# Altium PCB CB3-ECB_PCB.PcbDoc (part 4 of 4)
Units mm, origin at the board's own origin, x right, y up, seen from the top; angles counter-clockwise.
Board outline 195 x 139 mm, 4 copper layers (Top Layer, Layer 1, Layer 2, Bottom Layer), stack 1.56 mm thick; 363 components, 264 nets, 1430 pads, 630 vias.
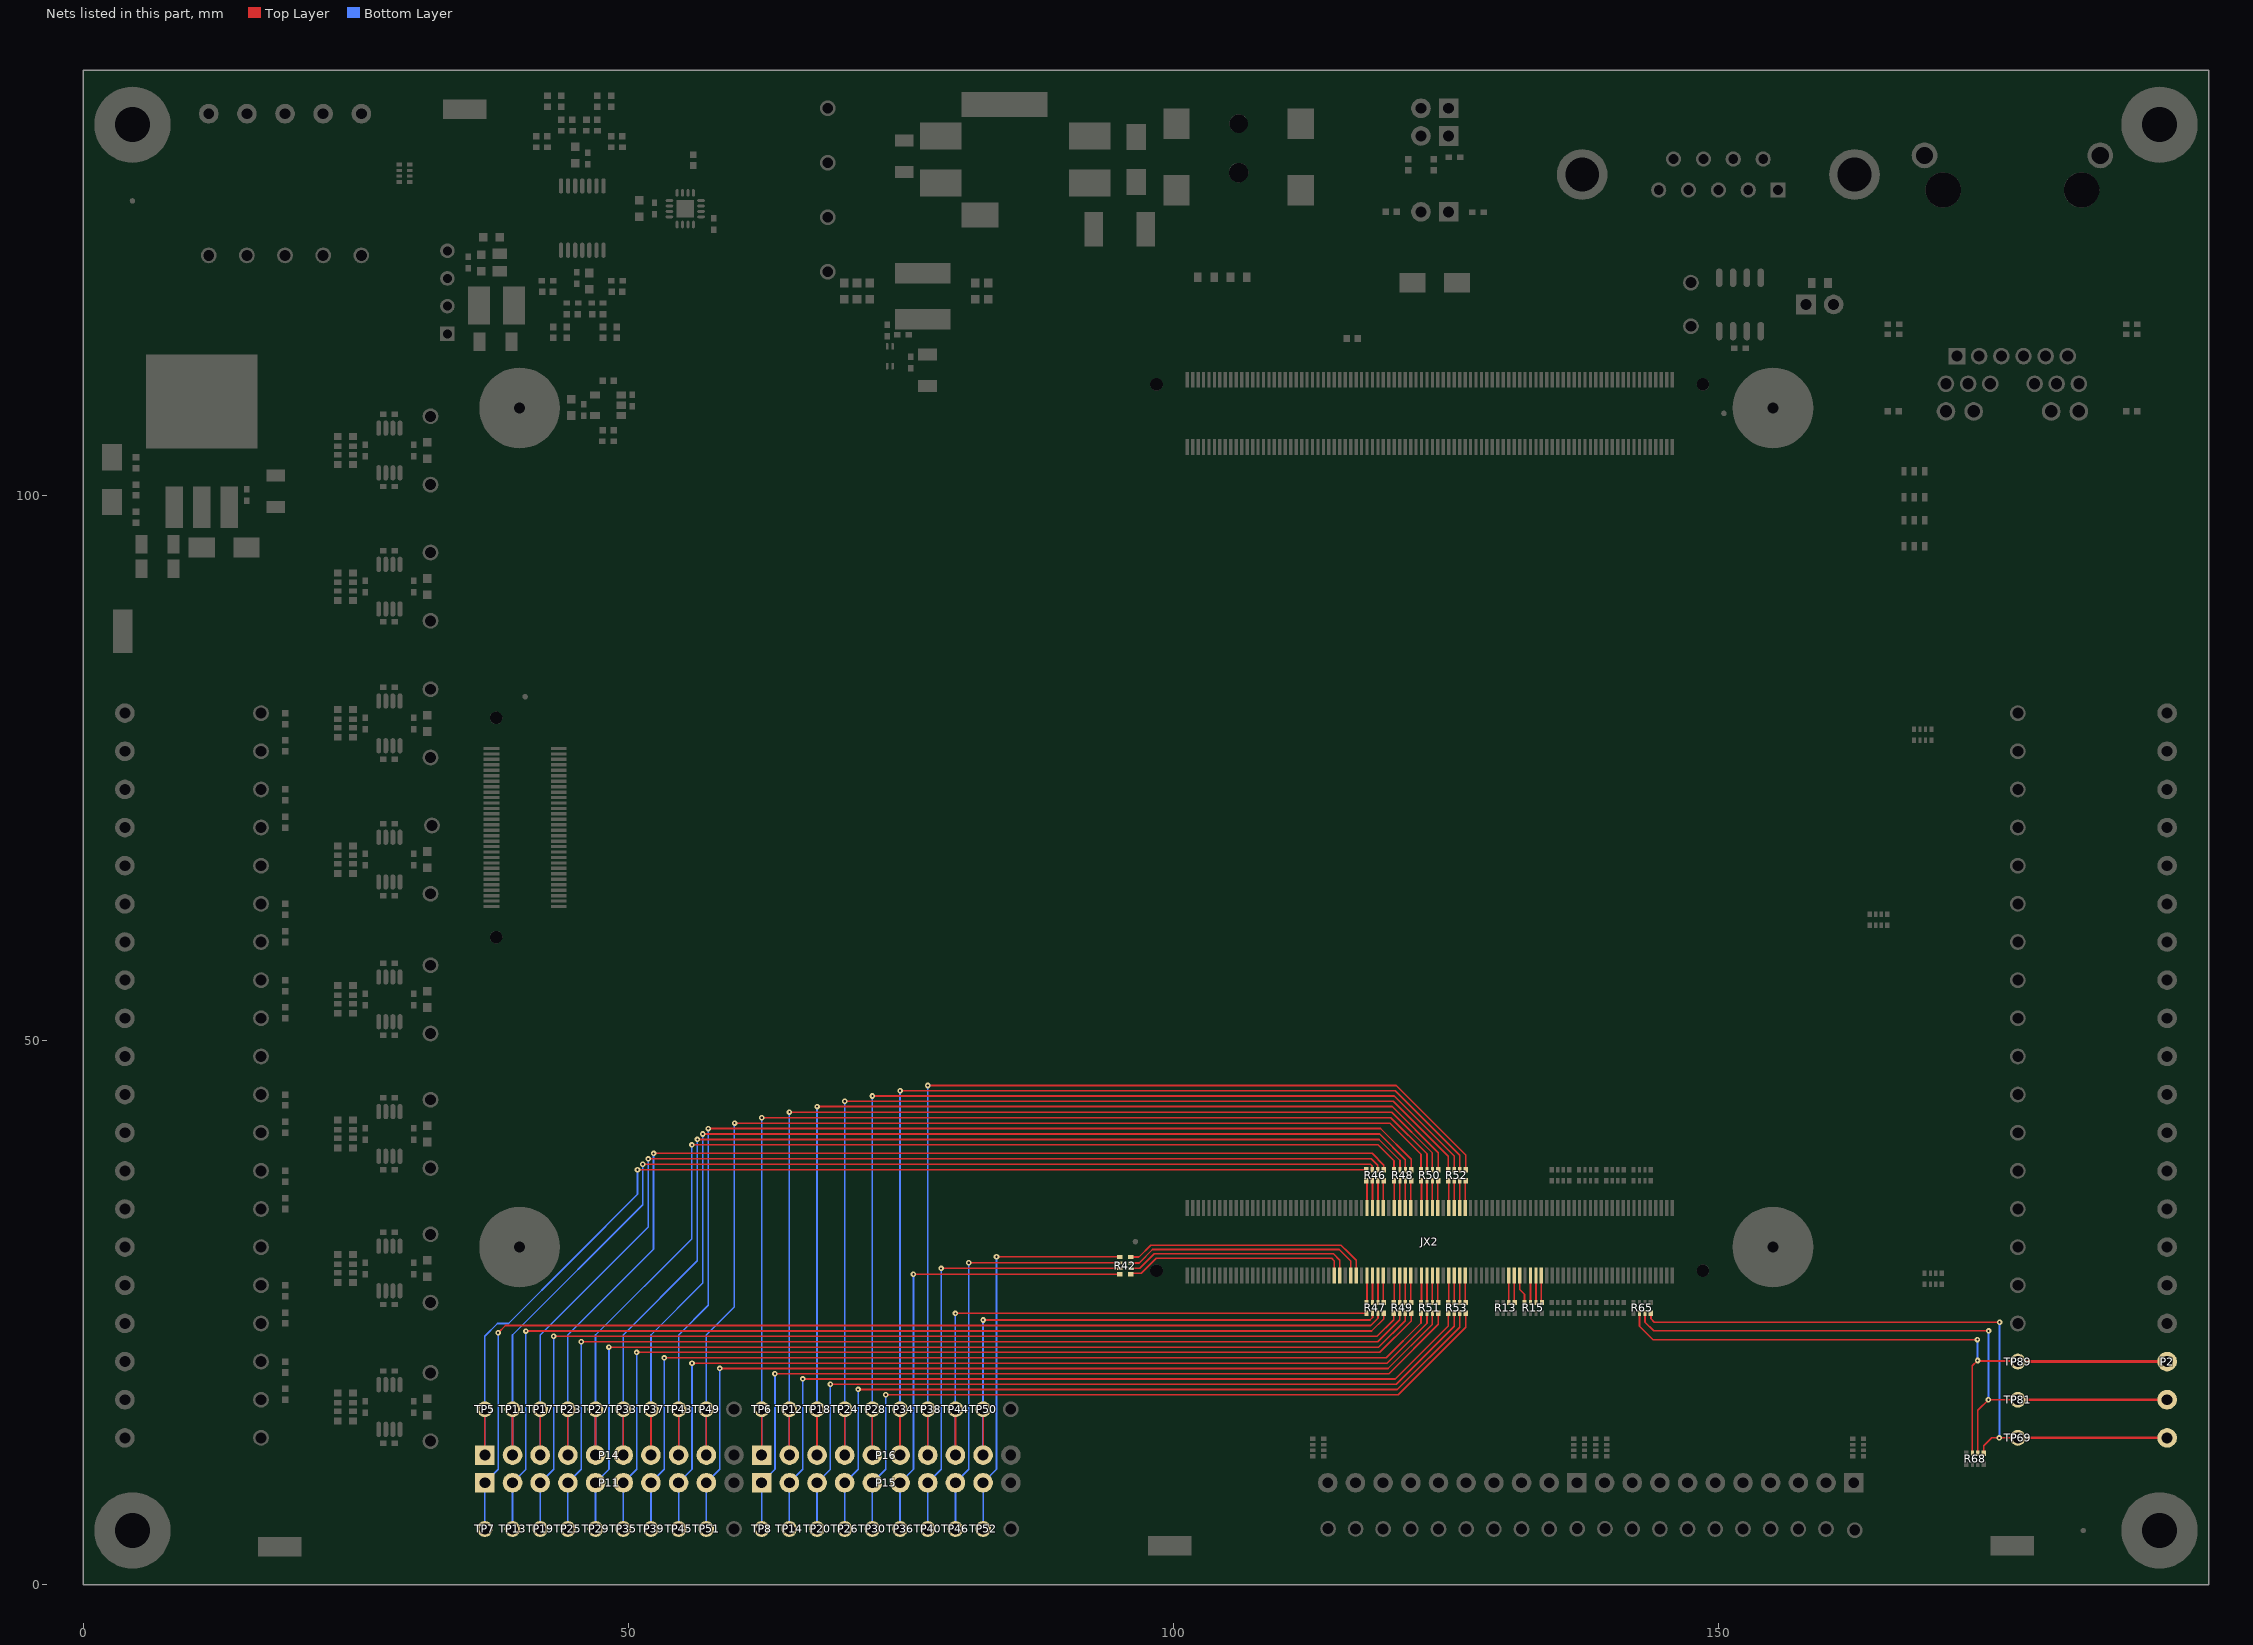
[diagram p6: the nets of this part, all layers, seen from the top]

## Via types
v1: diameter 0.508, hole 0.2, Top Layer to Bottom Layer, tented both sides, 435 vias
v2: diameter 0.508, hole 0.2, Top Layer to Bottom Layer, 194 vias
v3: diameter 0.66, hole 0.33, Top Layer to Bottom Layer, tented both sides, 1 vias

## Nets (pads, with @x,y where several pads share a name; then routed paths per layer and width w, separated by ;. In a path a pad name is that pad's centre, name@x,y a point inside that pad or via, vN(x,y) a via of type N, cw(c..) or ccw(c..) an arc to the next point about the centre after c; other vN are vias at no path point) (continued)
PWM-13: P2.3 R65.2 R68.3 TP89.1 | length 60.8
  Top Layer w0.152: R65.2@142.78,24.92 142.78,23.752 144.016,22.516 v1(173.794,22.516) ; R68.3@173.328,12.073 173.328,20.128 v1(173.8,20.6) 173.85,20.55 177.45,20.55 TP89.1@177.5,20.5
  Top Layer w0.25: TP89.1@177.5,20.5 P2.3@191.2,20.5
  Bottom Layer w0.152: v1(173.794,22.516) 173.797,22.514 173.797,20.603 v1(173.8,20.6)
PWM-14: P2.4 R65.3 R68.2 TP81.1 | length 60.7
  Top Layer w0.152: R65.3@143.28,24.92 143.28,24.117 144.083,23.315 v1(174.81,23.315) ; R68.2@173.828,12.073 173.828,16.028 v1(174.8,17) TP81.1@177.5,17
  Top Layer w0.25: TP81.1@177.5,17 P2.4@191.2,17
  Bottom Layer w0.152: v1(174.8,17) 174.805,17.005 174.805,23.31 v1(174.81,23.315)
PWM-15: P2.5 R65.4 R68.1 TP69.1 | length 61.1
  Top Layer w0.152: R65.4@143.83,24.92 143.83,24.432 144.149,24.113 v1(175.826,24.113) ; R68.1@174.378,12.073 174.378,12.784 175.094,13.5 TP69.1@177.5,13.5
  Top Layer w0.25: TP69.1@177.5,13.5 P2.5@191.2,13.5
  Bottom Layer w0.152: v1(175.8,13.5) 175.813,13.513 175.813,24.1 v1(175.826,24.113)
SPI1_LATCH: JX2.121 R13.2 | length 2.5
  Top Layer w0.152: R13.2@130.78,25.92 JX2.121@130.78,28.41
SPI1_MISO: JX2.120 R13.1 | length 2.5
  Top Layer w0.152: JX2.120@131.28,28.41 131.28,25.97 R13.1@131.33,25.92
SPI1_MOSI: JX2.116 R15.2 | length 2.5
  Top Layer w0.152: R15.2@133.28,25.92 JX2.116@133.28,28.41
SPI1_nCS: JX2.117 R15.3 | length 2.5
  Top Layer w0.152: R15.3@132.78,25.92 JX2.117@132.78,28.41
SPI1_nRST: JX2.115 R15.1 | length 2.5
  Top Layer w0.152: JX2.115@133.78,28.41 133.78,25.97 R15.1@133.83,25.92
SPI1_SCLK: JX2.119 R15.4 | length 2.7
  Top Layer w0.152: JX2.119@131.78,28.41 131.78,27.12 132.23,26.67 R15.4@132.23,25.92
USER0: P14.1 R46.4 TP5.1 | length 104.3
  Top Layer w0.152: P14.1@36.834,11.921 TP5.1@36.834,16.76 ; v1(50.843,38.096) R46.4@117.72,38.096
  Bottom Layer w0.152: P14.1@36.834,11.921 36.834,16.76 36.834,17.954 36.834,22.834 38,24 39,24 45.041,30.041 50.843,35.843 v1(50.843,38.096)
USER1: P14.2 R46.3 TP11.1 | length 103.1
  Top Layer w0.152: P14.2@39.374,11.921 TP11.1@39.374,16.76 ; v1(51.327,38.603) 117.671,38.603 118.096,38.603 118.27,38.429 R46.3@118.27,38.096
  Bottom Layer w0.152: P14.2@39.374,11.921 TP11.1@39.374,16.024 ; TP11.1@39.374,16.786 39.374,20.24 39.374,22.945 51.327,34.897 v1(51.327,38.603)
USER2: P14.3 R46.2 TP17.1 | length 103.7
  Top Layer w0.152: P14.3@41.914,11.921 TP17.1@41.914,16.76 ; v1(51.82,39.103) 117.837,39.103 118.171,39.103 118.77,38.503 R46.2@118.77,38.096
  Bottom Layer w0.152: P14.3@41.914,11.921 41.914,16.938 41.914,22.945 51.82,32.851 v1(51.82,39.103)
USER3: P14.4 R46.1 TP23.1 | length 103.7
  Top Layer w0.152: P14.4@44.454,11.921 TP23.1@44.454,16.76 ; v1(52.314,39.603) 118.246,39.603 119.32,38.528 R46.1@119.32,38.096
  Bottom Layer w0.152: P14.4@44.454,11.921 44.454,22.945 52.314,30.804 v1(52.314,39.603)
USER4: P14.5 R48.4 TP27.1 | length 102.8
  Top Layer w0.152: P14.5@46.994,11.921 TP27.1@46.994,16.76 ; v1(55.834,40.381) 118.8,40.381 120.252,38.929 R48.4@120.252,38.096
  Bottom Layer w0.152: P14.5@46.994,11.921 46.994,22.945 55.834,31.785 v1(55.834,40.381)
USER5: P14.6 R48.3 TP33.1 | length 102.7
  Top Layer w0.152: P14.6@49.534,11.921 TP33.1@49.534,16.76 ; v1(56.334,40.881) 118.875,40.881 120.802,38.954 R48.3@120.802,38.096
  Bottom Layer w0.152: P14.6@49.534,11.921 49.534,22.945 56.334,29.745 v1(56.334,40.881)
USER6: P14.7 R48.2 TP37.1 | length 102.6
  Top Layer w0.152: P14.7@52.074,11.921 TP37.1@52.074,16.76 ; v1(56.834,41.381) 118.95,41.381 121.302,39.028 R48.2@121.302,38.096
  Bottom Layer w0.152: P14.7@52.074,11.921 52.074,22.945 56.834,27.705 v1(56.834,41.381)
USER7: P14.8 R48.1 TP43.1 | length 102.6
  Top Layer w0.152: P14.8@54.614,11.921 TP43.1@54.614,16.76 ; v1(57.334,41.881) 119.025,41.881 121.852,39.053 R48.1@121.852,38.096
  Bottom Layer w0.152: P14.8@54.614,11.921 54.614,22.945 57.334,25.665 v1(57.334,41.881)
USER8: P14.9 R50.4 TP49.1 | length 102
  Top Layer w0.152: P14.9@57.154,11.921 TP49.1@57.154,16.76 ; v1(59.745,42.381) 119.887,42.381 122.73,39.538 R50.4@122.73,38.096
  Bottom Layer w0.152: P14.9@57.154,11.921 57.154,22.945 59.734,25.525 v1@59.734,42.381
USER9: P16.1 R50.3 TP6.1 | length 99.7
  Top Layer w0.152: P16.1@62.234,11.921 TP6.1@62.234,16.76 ; v1(62.234,42.881) 119.656,42.881 119.962,42.881 123.28,39.562 R50.3@123.28,38.096
  Bottom Layer w0.152: P16.1@62.23,11.921 62.23,16.166 62.23,18.195 v1@62.23,42.881
USER10: P16.2 R50.2 TP12.1 | length 98.4
  Top Layer w0.152: P16.2@64.774,11.921 TP12.1@64.774,16.76 ; v1@64.774,43.381 120.036,43.381 123.78,39.637 R50.2@123.78,38.096
  Bottom Layer w0.152: P16.2@64.77,11.925 64.77,16.166 64.77,18.28 64.77,42.881 64.77,43.388 v1(64.774,43.392)
USER11: P16.3 R50.1 TP18.1 | length 97.2
  Top Layer w0.152: P16.3@67.314,11.921 TP18.1@67.314,16.76 ; v1@67.314,43.903 119.783,43.903 120.089,43.903 124.33,39.662 R50.1@124.33,38.096
  Bottom Layer w0.152: P16.3@67.31,11.925 67.31,16.166 67.31,18.195 67.31,42.381 67.31,43.896 v1(67.314,43.9)
USER12: P16.4 R52.4 TP24.1 | length 96
  Top Layer w0.152: P16.4@69.854,11.921 TP24.1@69.854,16.76 ; v1(69.854,44.386) 119.952,44.386 120.181,44.386 125.23,39.337 R52.4@125.23,38.096
  Bottom Layer w0.152: P16.4@69.85,11.925 69.85,16.166 69.85,18.195 v1@69.85,44.386
USER13: P16.5 R52.3 TP28.1 | length 94.7
  Top Layer w0.152: P16.5@72.394,11.921 TP28.1@72.394,16.76 ; v1(72.394,44.868) 120.12,44.868 120.273,44.868 125.78,39.361 R52.3@125.78,38.096
  Bottom Layer w0.152: P16.5@72.39,11.925 72.39,16.166 72.39,18.195 v1@72.39,44.868
USER14: P16.6 R52.2 TP34.1 | length 93.4
  Top Layer w0.152: P16.6@74.934,11.921 TP34.1@74.934,16.76 ; v1(74.934,45.351) 120.288,45.351 120.365,45.351 126.28,39.436 R52.2@126.28,38.096
  Bottom Layer w0.152: P16.6@74.93,11.925 74.93,16.166 v1@74.93,45.351
USER15: P16.7 R52.1 TP38.1 | length 92.1
  Top Layer w0.152: v1(77.47,45.834) 120.016,45.834 120.458,45.834 126.83,39.461 R52.1@126.83,38.096 ; P16.7@77.474,11.921 TP38.1@77.474,16.76
  Bottom Layer w0.152: P16.7@77.47,11.925 77.47,16.166 77.47,18.195 v1(77.47,45.834)
USER16: P16.8 R47.1 TP44.1 | length 55.6
  Top Layer w0.152: P16.8@80.014,11.921 TP44.1@80.014,16.76 ; v1@80.014,24.924 R47.1@117.73,24.92
  Bottom Layer w0.152: P16.8@80.01,11.925 v1(80.01,24.924)
USER17: P16.9 R47.2 TP50.1 | length 53.4
  Top Layer w0.152: v1(82.55,24.316) 117.987,24.316 118.057,24.316 118.28,24.539 R47.2@118.28,24.92 ; P16.9@82.554,11.921 TP50.1@82.554,16.76
  Bottom Layer w0.152: P16.9@82.55,11.925 v1(82.55,24.316)
USER18: P11.1 R47.3 TP7.1 | length 100.2
  Top Layer w0.152: v1@38.058,23.143 38.727,23.812 117.788,23.812 118.127,23.812 118.78,24.465 R47.3@118.78,24.92
  Bottom Layer w0.152: TP7.1@36.834,5.143 P11.1@36.834,9.381 38.063,10.61 38.063,23.138 v1(38.054,23.148)
USER19: P11.2 R47.4 TP13.1 | length 98.3
  Top Layer w0.152: v1(40.603,23.304) 117.981,23.304 118.194,23.304 119.33,24.44 R47.4@119.33,24.92
  Bottom Layer w0.152: TP13.1@39.374,5.143 P11.2@39.374,9.381 40.603,10.61 v1(40.603,23.304)
USER20: P11.3 R49.1 TP19.1 | length 96.5
  Top Layer w0.152: v1@43.143,22.821 118.351,22.821 118.702,22.821 120.23,24.349 R49.1@120.23,24.92
  Bottom Layer w0.152: TP19.1@41.914,5.143 P11.3@41.914,9.381 43.143,10.61 v1(43.143,22.818)
USER21: P11.4 R49.2 TP25.1 | length 94.2
  Top Layer w0.152: v1(45.683,22.313) 118.519,22.313 118.769,22.313 120.78,24.325 R49.2@120.78,24.92
  Bottom Layer w0.152: TP25.1@44.454,5.143 P11.4@44.454,9.381 45.683,10.61 v1(45.683,22.313)
USER22: P11.5 R49.3 TP29.1 | length 91.9
  Top Layer w0.152: v1(48.223,21.831) 118.687,21.831 118.861,21.831 121.28,24.25 R49.3@121.28,24.92
  Bottom Layer w0.152: TP29.1@46.994,5.143 P11.5@46.994,9.381 48.223,10.61 v1(48.223,21.831)
USER23: P11.6 R49.4 TP35.1 | length 89.7
  Top Layer w0.152: v1@50.763,21.348 118.953,21.348 121.83,24.225 R49.4@121.83,24.92
  Bottom Layer w0.152: TP35.1@49.534,5.143 P11.6@49.534,9.381 50.763,10.61 v1(50.763,21.344)
USER24: P11.7 R51.1 TP39.1 | length 87.8
  Top Layer w0.152: v1(53.303,20.84) 119.532,20.84 122.73,24.038 R51.1@122.73,24.92
  Bottom Layer w0.152: TP39.1@52.074,5.143 P11.7@52.074,9.381 53.303,10.61 v1(53.303,20.84)
USER25: P11.8 R51.2 TP45.1 | length 85.6
  Top Layer w0.152: v1(55.843,20.354) 119.164,20.354 119.621,20.354 123.28,24.013 R51.2@123.28,24.92
  Bottom Layer w0.152: TP45.1@54.614,5.143 P11.8@54.614,9.381 55.843,10.61 v1(55.843,20.354)
USER26: P11.9 R51.3 TP51.1 | length 83.3
  Top Layer w0.152: v1(58.383,19.871) 61.041,19.871 119.713,19.871 123.78,23.939 R51.3@123.78,24.92
  Bottom Layer w0.152: TP51.1@57.154,5.143 P11.9@57.154,9.381 58.383,10.61 v1(58.383,19.871)
USER27: P15.1 R51.4 TP8.1 | length 78.5
  Top Layer w0.152: v1(63.454,19.389) 119.805,19.389 124.33,23.914 R51.4@124.33,24.92
  Bottom Layer w0.152: TP8.1@62.234,5.143 P15.1@62.234,9.381 63.463,10.61 v1@63.463,19.389
USER28: P15.2 R53.1 TP14.1 | length 76.7
  Top Layer w0.152: v1(66.003,18.906) 120.375,18.906 125.23,23.761 R53.1@125.23,24.92
  Bottom Layer w0.152: TP14.1@64.774,5.143 P15.2@64.774,9.381 66.003,10.61 v1(66.003,18.906)
USER29: P15.3 R53.2 TP20.1 | length 74.5
  Top Layer w0.152: v1@68.543,18.246 68.721,18.423 119.989,18.423 120.467,18.423 125.78,23.737 R53.2@125.78,24.92
  Bottom Layer w0.152: TP20.1@67.314,5.143 P15.3@67.314,9.381 68.543,10.61 v1(68.543,18.423)
USER30: P15.4 R53.3 TP26.1 | length 72.1
  Top Layer w0.152: v1(71.083,17.941) 120.082,17.941 120.559,17.941 126.28,23.662 R53.3@126.28,24.92
  Bottom Layer w0.152: TP26.1@69.854,5.143 P15.4@69.854,9.381 71.083,10.61 v1(71.083,17.941)
USER31: P15.5 R53.4 TP30.1 | length 69.9
  Top Layer w0.152: v1(73.623,17.458) 120.174,17.458 120.651,17.458 126.83,23.637 R53.4@126.83,24.92
  Bottom Layer w0.152: TP30.1@72.394,5.143 P15.5@72.394,9.381 73.623,10.61 v1(73.623,17.458)
USER32: P15.6 R42.4 TP36.1 | length 42.8
  Top Layer w0.152: v1(76.163,28.512) 95.088,28.512 R42.4@95.1,28.5
  Bottom Layer w0.152: TP36.1@74.934,5.143 P15.6@74.934,9.381 76.163,10.61 v1(76.163,28.512)
USER33: P15.7 R42.3 TP40.1 | length 40.8
  Top Layer w0.152: v1@78.703,29.062 95.088,29.062 R42.3@95.1,29.05
  Bottom Layer w0.152: TP40.1@77.474,5.143 P15.7@77.474,9.381 78.703,10.61 v1(78.703,29.054) v1@78.703,29.062
USER34: P15.8 R42.2 TP46.1 | length 38.8
  Top Layer w0.152: v1(81.243,29.562) 95.088,29.562 R42.2@95.1,29.55
  Bottom Layer w0.152: TP46.1@80.014,5.143 P15.8@80.014,9.381 81.243,10.61 v1(81.243,29.562)
USER35: P15.9 R42.1 TP52.1 | length 36.8
  Top Layer w0.152: v1(83.783,30.112) 95.088,30.112 R42.1@95.1,30.1
  Bottom Layer w0.152: TP52.1@82.554,5.143 P15.9@82.554,9.381 83.783,10.61 v1(83.783,30.112) v1@83.783,30.121
USR0: JX2.34 R46.5 | length 2.5
  Top Layer w0.152: JX2.34@117.78,34.6 R46.5@117.78,37.096
USR1: JX2.35 R46.6 | length 2.5
  Top Layer w0.152: JX2.35@118.28,34.6 R46.6@118.28,37.096
USR2: JX2.36 R46.7 | length 2.5
  Top Layer w0.152: JX2.36@118.78,34.6 R46.7@118.78,37.096
USR3: JX2.37 R46.8 | length 2.5
  Top Layer w0.152: JX2.37@119.28,34.6 R46.8@119.28,37.096
USR4: JX2.39 R48.5 | length 2.5
  Top Layer w0.152: JX2.39@120.28,34.6 R48.5@120.28,37.096
USR5: JX2.40 R48.6 | length 2.5
  Top Layer w0.152: JX2.40@120.78,34.6 R48.6@120.78,37.096
USR6: JX2.41 R48.7 | length 2.5
  Top Layer w0.152: JX2.41@121.28,34.6 R48.7@121.28,37.096
USR7: JX2.42 R48.8 | length 2.5
  Top Layer w0.152: JX2.42@121.78,34.6 R48.8@121.78,37.096
USR8: JX2.44 R50.5 | length 2.5
  Top Layer w0.152: JX2.44@122.78,34.6 R50.5@122.78,37.096
USR9: JX2.45 R50.6 | length 2.5
  Top Layer w0.152: JX2.45@123.28,34.6 R50.6@123.28,37.096
USR10: JX2.46 R50.7 | length 2.5
  Top Layer w0.152: JX2.46@123.78,34.6 R50.7@123.78,37.096
USR11: JX2.47 R50.8 | length 2.5
  Top Layer w0.152: JX2.47@124.28,34.6 R50.8@124.28,37.096
USR12: JX2.49 R52.5 | length 2.5
  Top Layer w0.152: JX2.49@125.28,34.6 R52.5@125.28,37.096
USR13: JX2.50 R52.6 | length 2.5
  Top Layer w0.152: JX2.50@125.78,34.6 R52.6@125.78,37.096
USR14: JX2.51 R52.7 | length 2.5
  Top Layer w0.152: JX2.51@126.28,34.6 R52.7@126.28,37.096
USR15: JX2.52 R52.8 | length 2.5
  Top Layer w0.152: JX2.52@126.78,34.6 R52.8@126.78,37.096
USR16: JX2.147 R47.8 | length 2.5
  Top Layer w0.152: R47.8@117.78,25.92 JX2.147@117.78,28.41
USR17: JX2.146 R47.7 | length 2.5
  Top Layer w0.152: R47.7@118.28,25.92 JX2.146@118.28,28.41
USR18: JX2.145 R47.6 | length 2.5
  Top Layer w0.152: R47.6@118.78,25.92 JX2.145@118.78,28.41
USR19: JX2.144 R47.5 | length 2.5
  Top Layer w0.152: R47.5@119.28,25.92 JX2.144@119.28,28.41
USR20: JX2.142 R49.8 | length 2.5
  Top Layer w0.152: R49.8@120.28,25.92 JX2.142@120.28,28.41
USR21: JX2.141 R49.7 | length 2.5
  Top Layer w0.152: R49.7@120.78,25.92 JX2.141@120.78,28.41
USR22: JX2.140 R49.6 | length 2.5
  Top Layer w0.152: R49.6@121.28,25.92 JX2.140@121.28,28.41
USR23: JX2.139 R49.5 | length 2.5
  Top Layer w0.152: R49.5@121.78,25.92 JX2.139@121.78,28.41
USR24: JX2.137 R51.8 | length 2.5
  Top Layer w0.152: R51.8@122.78,25.92 JX2.137@122.78,28.41
USR25: JX2.136 R51.7 | length 2.5
  Top Layer w0.152: R51.7@123.28,25.92 JX2.136@123.28,28.41
USR26: JX2.135 R51.6 | length 2.5
  Top Layer w0.152: R51.6@123.78,25.92 JX2.135@123.78,28.41
USR27: JX2.134 R51.5 | length 2.5
  Top Layer w0.152: R51.5@124.28,25.92 JX2.134@124.28,28.41
USR28: JX2.132 R53.8 | length 2.5
  Top Layer w0.152: R53.8@125.28,25.92 JX2.132@125.28,28.41
USR29: JX2.131 R53.7 | length 2.5
  Top Layer w0.152: R53.7@125.78,25.92 JX2.131@125.78,28.41
USR30: JX2.130 R53.6 | length 2.5
  Top Layer w0.152: R53.6@126.28,25.92 JX2.130@126.28,28.41
USR31: JX2.129 R53.5 | length 2.5
  Top Layer w0.152: R53.5@126.78,25.92 JX2.129@126.78,28.41
USR32: JX2.153 R42.5 | length 20.7
  Top Layer w0.152: R42.5@96.1,28.5 96.214,28.614 97.071,28.614 98.435,29.978 114.532,29.978 114.78,29.73 JX2.153@114.78,28.41
USR33: JX2.152 R42.6 | length 21.4
  Top Layer w0.152: R42.6@96.1,29.05 96.938,29.05 98.269,30.381 114.705,30.381 115.28,29.805 JX2.152@115.28,28.41
USR34: JX2.150 R42.7 | length 22.4
  Top Layer w0.152: R42.7@96.1,29.55 96.869,29.55 98.102,30.783 115.227,30.783 116.28,29.73 JX2.150@116.28,28.41
USR35: JX2.149 R42.8 | length 23.1
  Top Layer w0.152: R42.8@96.1,30.1 96.85,30.1 97.935,31.185 115.4,31.185 116.09,30.495 116.78,29.805 JX2.149@116.78,28.41
pads on no net: F1.0 F2.0 F3.0 F4.0 F5.0 J6.NC JX1.4 JX1.5 JX1.7 JX1.8 JX1.22 JX1.23 JX1.24 JX1.25 JX1.27 JX1.28 JX1.29 JX1.30 JX1.32 JX1.33 JX1.34 JX1.35 JX1.37 JX1.38 JX1.39 JX1.40 JX1.42 JX1.43 JX1.45 JX1.46 JX1.48 JX1.49 JX1.51 JX1.52 JX1.54 JX1.55 JX1.56 JX1.57 JX1.59 JX1.60 JX1.61 JX1.62 JX1.64 JX1.65 JX1.66 JX1.67 JX1.69 JX1.70 JX1.71 JX1.72 JX1.74 JX1.75 JX1.76 JX1.77 JX1.79 JX1.80 JX1.81 JX1.82 JX1.84 JX1.85 JX1.86 JX1.87 JX1.94 JX1.95 JX1.96 JX1.97 JX1.99 JX1.100 JX1.101 JX1.102 JX1.104 JX1.105 JX1.106 JX1.107 JX1.109 JX1.110 JX1.111 JX1.112 JX1.114 JX1.115 JX1.116 JX1.117 JX1.119 JX1.120 JX1.121 JX1.122 JX1.124 JX1.125 JX1.126 JX1.127 JX1.129 JX1.130 JX1.132 JX1.133 JX1.135 JX1.136 JX1.138 JX1.139 JX1.141 JX1.142 JX1.143 JX1.144 JX1.146 JX1.147 JX1.148 JX1.149 JX1.151 JX1.152 JX1.153 JX1.154 JX1.156 JX1.157 JX1.158 JX1.159 JX1.161 JX1.162 JX1.164 JX1.165 JX1.170 JX1.171 JX1.173 JX1.174 JX1.H1 JX1.H2 JX2.5 JX2.6 JX2.9 JX2.10 JX2.54 JX2.55 JX2.56 JX2.57 JX2.58 JX2.60 JX2.61 JX2.62 JX2.64 JX2.65 JX2.66 JX2.123 JX2.124 JX2.125 JX2.126 JX2.127 JX2.H1 JX2.H2 JX3.2 JX3.3 JX3.5 JX3.6 JX3.7 JX3.8 JX3.53 JX3.54 JX3.55 JX3.56 JX3.58 JX3.59 JX3.NC P10.1 P10.4 P10.5 P10.8 P10.9 P19.H1 P19.H2 R13.3 R13.4 R13.5 R13.6 U12.2 U17.5 U17.8

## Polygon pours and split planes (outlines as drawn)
5V2 on Top Layer "5V2_L01_P001" (solid, pour order 1): 0.25,117 22.25,117 22.25,103 0.25,103
GND on Top Layer "GND_L01_P000" (solid, pour order 0): 89,139 89,122.3 73,122.3 73,127.1 80.9,127.1 80.9,130.2 73,130.2 73,139
5V2 on Layer 2 "5V2_L03_P007" (solid, remove dead copper, pour order 7): 40,126 40,121.5 37.75,121.5 37.75,126 1.425,126 1.425,91.75 27,91.75 27,10 34.75,10 34.75,57.5 45.25,57.5 45.25,81.5 34.75,81.5 34.75,102 47,102 47,108.25 40,108.25 40,106 27,106 27,97.25 15.5,97.25 15.5,103 22.25,103 22.25,118.25 22.5,118.5 52.25,118.5 52.25,132.75 63.25,132.75 63.25,124.25 69.5,124.25 69.5,129 65,129 65,133.75 49,133.75 49,126
3V3 on Layer 2 "3V3_L03_P004" (solid, pour order 4): 124,122.25 124,134.23 127.75,134.23 127.75,122.25 190.5,122.25 190.5,107 188.5,107 188.5,118 166,118 166,105.5 169.25,105.5 169.25,94.25 166.75,94.25 166.75,102.75 161.75,102.75 161.75,111.5 116.99,111.5 116.99,117.75 81.25,117.75 81.25,122.25
+12V on Layer 2 "+12V_L03_P003" (solid, pour order 3): 73,118.25 22.5,118.25 22.5,102.75 15.75,102.75 15.75,97.5 26.75,97.5 26.75,106.25 39.75,106.25 39.75,108.5 73,108.5 73,95.5 99,95.5 99,25 116.75,25 116.75,117.5 81,117.5 81,130 73,130 73,137 67,137 67,133.25 69.75,133.25 69.75,124.25 73,124.25
3V3 on Layer 2 "3V3_L03_P005" (solid, pour order 5): 52.5,132.5 63,132.5 63,124 72.75,124 72.75,118.5 52.5,118.5
-5V on Layer 2 "-5V_L03_P006" (solid, pour order 6): 66.75,135 66.75,133 69.5,133 69.5,129.25 65.25,129.25 65.25,134 48.75,134 48.75,126.25 39.75,126.25 39.75,121.75 38,121.75 38,133 38,135
GND on Layer 2 "GND_L03_P008" (solid, pour order 8): 0,139 195,139 195,0 0,0
GND on Layer 1 "GND_L02_P010" (solid, pour order 10): 0,0 195,0 195,139 0,139

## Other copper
Top Layer:
  rectangle net GND: 80.875,116.5 84,118.375
  rectangle net GND: 72.8,112.25 73.375,112.615
  rectangle net GND: 68.85,116.5 73.1,118.375
  rectangle net 3V3: 67.5,119.075 86,121.675
  rectangle net NetC58_1: 75.425,113.2 76.375,115.5
  rectangle net NetC58_1: 74.675,113.2 76.375,113.975
  rectangle net +12V: 76.2,109.475 78.45,110.975
  rectangle net +12V: 74.7,109.475 76.45,112.225
  rectangle net GND: 71.7,112.496 78.2,113.004
  rectangle net +12V: 73,127.3 80.7,130
  pour cut-out: 24.741,90.207 25.191,90.207 25.934,89.464 26.024,89.427 26.97,89.427 26.97,88.724 27.007,88.634 27.434,88.207 ccw(c27.524,88.297) 27.652,88.297 27.614,88.387 27.225,88.777 27.225,89.554 ccw(c27.097,89.554) 27.097,89.682 26.077,89.682 25.334,90.424 25.244,90.462 24.869,90.462 24.869,91.204 ccw(c24.741,91.204) 24.614,91.204 24.614,90.334 ccw(c24.741,90.334)
Layer 1:
  pour cut-out: 27.275,17.652 27.375,17.752 27.375,19.227 27.5,19.352 27.9,19.352 27.9,19.952 27.15,19.952 27.15,19.527 26.8,19.177 26.8,18.552 25.95,18.552 25.175,17.777 25.175,18.002 24.325,18.002 24.325,16.427 25.175,16.427 25.175,17.452 25.35,17.452 26.1,18.202 26.8,18.202 26.8,17.777 26.925,17.652
  pour cut-out: 27.275,30.365 27.375,30.465 27.375,31.94 27.5,32.065 27.9,32.065 27.9,32.665 27.15,32.665 27.15,32.24 26.8,31.89 26.8,31.265 25.95,31.265 25.175,30.49 25.175,30.715 24.325,30.715 24.325,29.14 25.175,29.14 25.175,30.165 25.35,30.165 26.1,30.915 26.8,30.915 26.8,30.49 26.925,30.365
  pour cut-out: 27.275,42.709 27.375,42.809 27.375,44.284 27.5,44.409 27.9,44.409 27.9,45.009 27.15,45.009 27.15,44.584 26.8,44.234 26.8,43.609 25.95,43.609 25.175,42.834 25.175,43.059 24.325,43.059 24.325,41.484 25.175,41.484 25.175,42.509 25.35,42.509 26.1,43.259 26.8,43.259 26.8,42.834 26.925,42.709
  pour cut-out: 27.275,55.054 27.375,55.154 27.375,56.629 27.5,56.754 27.9,56.754 27.9,57.354 27.15,57.354 27.15,56.929 26.8,56.579 26.8,55.954 25.95,55.954 25.175,55.179 25.175,55.404 24.325,55.404 24.325,53.829 25.175,53.829 25.175,54.854 25.35,54.854 26.1,55.604 26.8,55.604 26.8,55.179 26.925,55.054
  pour cut-out: 27.275,67.881 27.375,67.981 27.375,69.456 27.5,69.581 27.9,69.581 27.9,70.181 27.15,70.181 27.15,69.756 26.8,69.406 26.8,68.781 25.95,68.781 25.175,68.006 25.175,68.231 24.325,68.231 24.325,66.656 25.175,66.656 25.175,67.681 25.35,67.681 26.1,68.431 26.8,68.431 26.8,68.006 26.925,67.881
  pour cut-out: 27.275,80.377 27.375,80.477 27.375,81.952 27.5,82.077 27.9,82.077 27.9,82.677 27.15,82.677 27.15,82.252 26.8,81.902 26.8,81.277 25.95,81.277 25.175,80.502 25.175,80.727 24.325,80.727 24.325,79.152 25.175,79.152 25.175,80.177 25.35,80.177 26.1,80.927 26.8,80.927 26.8,80.502 26.925,80.377
  pour cut-out: 27.275,105.422 27.375,105.522 27.375,106.997 27.5,107.122 27.9,107.122 27.9,107.722 27.15,107.722 27.15,107.297 26.8,106.947 26.8,106.322 25.95,106.322 25.175,105.547 25.175,105.772 24.325,105.772 24.325,104.197 25.175,104.197 25.175,105.222 25.35,105.222 26.1,105.972 26.8,105.972 26.8,105.547 26.925,105.422
  pour cut-out: 27.275,102.781 27.375,102.681 27.375,101.206 27.409,101.172 27.9,101.172 27.9,100.597 27.15,100.597 27.15,100.906 26.8,101.256 26.8,101.881 25.95,101.881 25.175,102.656 25.175,102.431 24.325,102.431 24.325,104.006 25.175,104.006 25.175,102.981 25.35,102.981 26.1,102.231 26.8,102.231 26.8,102.656 26.925,102.781
  pour cut-out: 27.275,15.011 27.375,14.911 27.375,13.436 27.409,13.402 27.9,13.402 27.9,12.827 27.15,12.827 27.15,13.136 26.8,13.486 26.8,14.111 25.95,14.111 25.175,14.886 25.175,14.661 24.325,14.661 24.325,16.236 25.175,16.236 25.175,15.211 25.35,15.211 26.1,14.461 26.8,14.461 26.8,14.886 26.925,15.011
  pour cut-out: 27.275,27.724 27.375,27.624 27.375,26.149 27.409,26.115 27.9,26.115 27.9,25.54 27.15,25.54 27.15,25.849 26.8,26.199 26.8,26.824 25.95,26.824 25.175,27.599 25.175,27.374 24.325,27.374 24.325,28.949 25.175,28.949 25.175,27.924 25.35,27.924 26.1,27.174 26.8,27.174 26.8,27.599 26.925,27.724
  pour cut-out: 27.275,40.068 27.375,39.968 27.375,38.493 27.409,38.459 27.9,38.459 27.9,37.884 27.15,37.884 27.15,38.193 26.8,38.543 26.8,39.168 25.95,39.168 25.175,39.943 25.175,39.718 24.325,39.718 24.325,41.293 25.175,41.293 25.175,40.268 25.35,40.268 26.1,39.518 26.8,39.518 26.8,39.943 26.925,40.068
  pour cut-out: 27.275,52.412 27.375,52.312 27.375,50.837 27.409,50.804 27.9,50.804 27.9,50.229 27.15,50.229 27.15,50.537 26.8,50.887 26.8,51.512 25.95,51.512 25.175,52.287 25.175,52.062 24.325,52.062 24.325,53.637 25.175,53.637 25.175,52.612 25.35,52.612 26.1,51.862 26.8,51.862 26.8,52.287 26.925,52.412
  pour cut-out: 27.275,65.239 27.375,65.139 27.375,63.664 27.409,63.631 27.9,63.631 27.9,63.056 27.15,63.056 27.15,63.364 26.8,63.714 26.8,64.339 25.95,64.339 25.175,65.114 25.175,64.889 24.325,64.889 24.325,66.464 25.175,66.464 25.175,65.439 25.35,65.439 26.1,64.689 26.8,64.689 26.8,65.114 26.925,65.239
  pour cut-out: 27.275,77.736 27.375,77.636 27.375,76.161 27.409,76.127 27.9,76.127 27.9,75.552 27.15,75.552 27.15,75.861 26.8,76.211 26.8,76.836 25.95,76.836 25.175,77.611 25.175,77.386 24.325,77.386 24.325,78.961 25.175,78.961 25.175,77.936 25.35,77.936 26.1,77.186 26.8,77.186 26.8,77.611 26.925,77.736
  pour cut-out: 27.275,90.284 27.375,90.184 27.375,88.709 27.409,88.675 27.9,88.675 27.9,88.1 27.15,88.1 27.15,88.409 26.8,88.759 26.8,89.384 25.95,89.384 25.175,90.159 25.175,89.934 24.325,89.934 24.325,91.509 25.175,91.509 25.175,90.484 25.35,90.484 26.1,89.734 26.8,89.734 26.8,90.159 26.925,90.284
  pour cut-out: 27.275,92.925 27.375,93.025 27.375,94.5 27.5,94.625 27.9,94.625 27.9,95.225 27.15,95.225 27.15,94.8 26.8,94.45 26.8,93.825 25.95,93.825 25.175,93.05 25.175,93.275 24.325,93.275 24.325,91.7 25.175,91.7 25.175,92.725 25.35,92.725 26.1,93.475 26.8,93.475 26.8,93.05 26.925,92.925
Multi-Layer:
  pour cut-out: 89.3,139 89.3,122.3 113.8,122.3 113.8,139

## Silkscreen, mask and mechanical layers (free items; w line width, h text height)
Top Overlay:
  region: 64.886,122.524 64.886,118.562 66.867,120.543
  region: 64.886,127.507 64.886,123.544 66.867,125.525
  region: 64.886,132.489 64.886,128.526 66.867,130.508
  region: 64.886,137.471 64.886,133.509 66.867,135.49
  lines w0.254: 64.886,118.562 66.867,120.543 64.886,122.524 64.886,118.562 ; 64.886,123.544 64.886,127.507 66.867,125.525 64.886,123.544 ; 64.886,128.526 64.886,132.489 66.867,130.508 64.886,128.526 ; 64.886,133.509 64.886,137.471 66.867,135.49 64.886,133.509
  lines w0.4: 167.713,84.266 167.713,86.688 182.787,86.688 182.787,84.266 167.713,84.266
  lines w0.5: 8.5,116.9 8.5,138.2 28,138.2 28,116.9 ; 22.1,10.5 0.8,10.5 0.8,82.75 22.1,82.75 ; 34.902,3.212 87.302,3.314 87.302,20.967 ; 34.902,3.314 34.902,20.967 ; 98.5,121.45 98.5,138.2 113.5,138.2 113.5,121.45 ; 111.61,20.967 111.61,3.212 164.823,3.212 164.823,20.967 ; 115.5,121.45 115.5,138.2 132.5,138.2 132.5,121.45 ; 134.5,121.45 134.5,138.2 165.5,138.2 165.5,121.45 ; 138.229,3.212 138.229,19.443 ; 167.5,103.75 167.5,138.2 186.5,138.2 186.5,103.75 ; 172.9,10.5 194.2,10.5 194.2,82.75 172.9,82.75
  lines w0.508: 160,113 35.03,113 35.03,26 160.03,26 160.03,113 ; 1.798,84.562 1.798,90.404 7.386,90.404 7.386,84.562 1.798,84.562 ; 15.096,1.698 20.938,1.698 20.938,7.286 15.096,7.286 15.096,1.698 ; 32.096,131.614 32.096,137.202 37.938,137.202 37.938,131.614 32.096,131.614 ; 96.766,1.798 96.766,7.386 102.608,7.386 102.608,1.798 96.766,1.798 ; 174.096,1.798 174.096,7.386 179.938,7.386 179.938,1.798 174.096,1.798
  text "GND" at 117.283,134.968 h1.8
  text "IN" at 127.6,134.968 h1.8
  text "12V" at 60.061,134.677 h2.5
  text "3V3" at 127.601,132.436 h1.8
  text "OUT" at 117.446,132.428 h1.8
  text "GND" at 32.096,131.584 h2.5
  text "-5V" at 60.061,129.681 h2.5
  text "Force Fault" at 120.313,127.946 h1.8
  text "5.2V" at 60.061,124.685 h2.5
  text "3" at 11.169,123.466 h1.8
  text "0" at 21.641,123.466 h1.8
  text "2" at 14.662,123.45 h1.8
  text "1" at 18.323,123.45 h1.8
  text "GND" at 23.942,123.46 h1.8
  text "POWER 12V" at 98.5,121.2 h2.5
  text "FAULTS" at 115.5,121.2 h2.5
  text "CAN BUS" at 134.5,121.2 h2.5
  text "3.3V" at 60.061,119.689 h2.5
  text "CAN_TX" at 140.52,119.058 h1.8
  text "Power ON" at 102.685,117.968 h1.8
  text "DAC" at 8.5,116.65 h2.5
  text "CAN_RX" at 140.458,115.058 h1.8
  text "Termination" at 155.219,114.465 h1.8
  text "7-" at 31.408,108.435 h1.8
  text "ETHERNET" at 167.5,103.5 h2.5
  text "JX1" at 97.918,102.401 h1.8
  text "7+" at 31.19,98.767 h1.8
  text "6-" at 31.388,95.954 h1.8
  text "GND" at 5.204,90.429 h2.5 r270
  text "imperix" at 161.212,89.922 h10
  text "reshaping energy" at 172.88,87.984 h2.5
  text "6+" at 31.17,86.287 h1.8
  text "CB3-ECB-.RevisionLetter" at 167.713,84.163 h2.54
  text "Copyright imperix, Sion, Switzerland - info@imperix.ch" at 193.5,83.9 h2 r90
  text "5-" at 31.396,83.407 h1.8
  text "ANALOG INPUTS" at 19.55,82.75 h2.5 r270
  text "7P" at 13.05,80.772 h1.8 r270
  text "GND" at 181.332,78.442 h1.8 r90
  text "7N" at 13.05,77.349 h1.8 r270
  text "0" at 181.313,76.141 h1.8 r90
  text "6P" at 13.066,73.792 h1.8 r270
  text "5+" at 31.178,73.739 h1.8
  text "1" at 181.312,72.823 h1.8 r90
  text "4-" at 31.373,70.894 h1.8
  text "6N" at 13.066,70.369 h1.8 r270
  text "2" at 181.321,69.162 h1.8 r90
  text "JX3" at 45.401,68.805 h1.8
  text "GND" at 13.06,67.558 h1.8 r270
  text "3" at 181.313,65.669 h1.8 r90
  text "5P" at 13.066,63.284 h1.8 r270
  text "4+" at 31.155,61.226 h1.8
  text "GND" at 181.332,60.942 h1.8 r90
  text "5N" at 13.066,59.86 h1.8 r270
  text "4" at 181.312,58.613 h1.8 r90
  text "3-" at 31.396,58.083 h1.8
  text "4P" at 13.05,56.307 h1.8 r270
  text "5" at 181.304,55.171 h1.8 r90
  text "4N" at 13.05,52.884 h1.8 r270
  text "6" at 181.312,51.636 h1.8 r90
  text "GND" at 13.06,50.058 h1.8 r270
  text "3+" at 31.178,48.415 h1.8
  text "7" at 181.312,48.166 h1.8 r90
  text "3P" at 13.066,45.784 h1.8 r270
  text "2-" at 31.396,45.722 h1.8
  text "GND" at 181.332,43.442 h1.8 r90
  text "3N" at 13.066,42.36 h1.8 r270
  text "8" at 181.313,41.141 h1.8 r90
  text "2P" at 13.05,38.784 h1.8 r270
  text "9" at 181.314,37.643 h1.8 r90
  text "2+" at 31.179,36.055 h1.8
  text "JX2" at 97.906,35.601 h1.8
  text "2N" at 13.05,35.36 h1.8 r270
  text "10" at 181.313,33.777 h1.8 r90
  text "1-" at 31.445,33.378 h1.8
  text "GND" at 13.06,32.558 h1.8 r270
  text "11" at 181.312,30.405 h1.8 r90
  text "1P" at 13.05,28.235 h1.8 r270
  text "GND" at 181.332,25.942 h1.8 r90
  text "1N" at 13.05,24.811 h1.8 r270
  text "1+" at 31.228,23.71 h1.8
  text "12" at 181.321,23.292 h1.8 r90
  text "0P" at 13.066,21.29 h1.8 r270
  text "0-" at 31.39,20.681 h1.8
  text "13" at 181.313,19.8 h1.8 r90
  text "USER" at 34.874,18.427 h2.5
  text "GPI                                  GPO" at 111.557,18.427 h2.5
  text "0N" at 13.066,17.866 h1.8 r270
  text "14" at 181.312,16.266 h1.8 r90
  text "GND" at 13.06,15.058 h1.8 r270
  text "GND" at 83.947,13.677 h1.8
  text "0" at 36.373,13.601 h1.8
  text "1" at 39.141,13.601 h1.8
  text "2" at 41.478,13.601 h1.8
  text "3" at 44.018,13.601 h1.8
  text "4" at 46.558,13.601 h1.8
  text "5" at 49.174,13.601 h1.8
  text "6" at 51.714,13.601 h1.8
  text "7" at 54.331,13.601 h1.8
  text "8" at 56.845,13.601 h1.8
  text "9" at 62.027,13.601 h1.8
  text "10" at 64.135,13.601 h1.8
  text "11" at 66.878,13.601 h1.8
  text "12" at 69.19,13.601 h1.8
  text "13" at 71.78,13.601 h1.8
  text "14" at 74.346,13.601 h1.8
  text "15" at 76.886,13.601 h1.8
  text "16" at 79.451,13.601 h1.8
  text "17" at 81.94,13.601 h1.8
  text "GND" at 58.344,13.576 h1.8
  text "15" at 181.304,12.801 h1.8 r90
  text "0+" at 31.173,11.014 h1.8
  text "PWM OUTPUTS" at 175.45,10.5 h2.5 r90
  text "GND" at 58.471,6.641 h1.8
  text "18" at 35.763,6.616 h1.8
  text "19" at 38.379,6.616 h1.8
  text "20" at 40.894,6.616 h1.8
  text "21" at 43.612,6.616 h1.8
  text "22" at 46.025,6.616 h1.8
  text "23" at 48.616,6.616 h1.8
  text "24" at 51.206,6.616 h1.8
  text "25" at 53.772,6.616 h1.8
  text "26" at 56.312,6.616 h1.8
  text "27" at 61.443,6.616 h1.8
  text "28" at 63.957,6.616 h1.8
  text "29" at 66.497,6.616 h1.8
  text "30" at 69.063,6.616 h1.8
  text "31" at 71.679,6.616 h1.8
  text "32" at 74.117,6.616 h1.8
  text "33" at 76.657,6.616 h1.8
  text "34" at 79.197,6.616 h1.8
  text "35" at 81.737,6.616 h1.8
  text "GND" at 84.023,6.616 h1.8
  text "6" at 144.348,6.474 h1.8
  text "5" at 146.914,6.474 h1.8
  text "4" at 149.428,6.474 h1.8
  text "3" at 151.968,6.474 h1.8
  text "2" at 154.534,6.474 h1.8
  text "1" at 157.277,6.474 h1.8
  text "0" at 159.588,6.474 h1.8
  text "7" at 116.307,6.449 h1.8
  text "6" at 118.821,6.449 h1.8
  text "5" at 121.387,6.449 h1.8
  text "4" at 123.901,6.449 h1.8
  text "3" at 126.441,6.449 h1.8
  text "2" at 129.007,6.449 h1.8
  text "1" at 131.75,6.449 h1.8
  text "0" at 133.807,6.464 h1.8
  text "GND" at 112.547,6.438 h1.8
  text "GND" at 135.153,6.438 h1.8
  text "GND" at 138.633,6.438 h1.8
  text "7" at 142.113,6.438 h1.8
  text "GND" at 161.29,6.438 h1.8
  text "GND" at 96.74,5.204 h2.5
  text "GND" at 174.07,5.204 h2.5
  text "GND" at 15.071,5.104 h2.5
Mechanical 1:
  the board outline again, w0.254
  text "4 layers PCB, Finished copper 1oz, Inner copper 1oz" at 0.225,155.9 h3
Drill Drawing:
  drawing of 157 lines, arcs and shapes, not listed
  text "Symbol" at 238.869,78.232 h1.83
  text "Count" at 251.718,78.232 h1.83
  text "Hole Size" at 266.7,78.232 h1.83
  text "Plated" at 295.902,78.232 h1.83
  text "Hole Type" at 308.751,78.232 h1.83
  text "Drill Layer Pair" at 327.389,78.232 h1.83
  text "Via/Pad" at 365.478,78.232 h1.83
  text "Pad Shape" at 380.46,78.232 h1.83
  text "Template" at 399.403,78.232 h1.83
  text "Description" at 428.859,78.232 h1.83
  text "Hole Tolerance (+)" at 450.544,78.232 h1.83
  text "Hole Tolerance (-)" at 484.418,78.232 h1.83
  text "1" at 251.718,74.422 h1.52
  text "12.99mil (0.330mm)" at 266.7,74.422 h1.52
  text "PTH" at 295.902,74.422 h1.52
  text "Round" at 308.751,74.422 h1.52
  text "Top Layer - Bottom Layer" at 327.389,74.422 h1.52
  text "Via" at 365.478,74.422 h1.52
  text "Rounded" at 380.46,74.422 h1.52
  text "v66h33m0mx0" at 399.403,74.422 h1.52
  text "B" at 238.13,74.168 h1.69
  text "1" at 251.718,70.612 h1.52
  text "66.93mil (1.700mm)" at 266.7,70.612 h1.52
  text "NPTH" at 295.902,70.612 h1.52
  text "Round" at 308.751,70.612 h1.52
  text "Top Layer - Bottom Layer" at 327.389,70.612 h1.52
  text "Pad" at 365.478,70.612 h1.52
  text "Rounded" at 380.46,70.612 h1.52
  text "c170hn170" at 399.403,70.612 h1.52
  text "1" at 251.718,66.802 h1.52
  text "70.87mil (1.800mm)" at 266.7,66.802 h1.52
  text "NPTH" at 295.902,66.802 h1.52
  text "Round" at 308.751,66.802 h1.52
  text "Top Layer - Bottom Layer" at 327.389,66.802 h1.52
  text "Pad" at 365.478,66.802 h1.52
  text "Rounded" at 380.46,66.802 h1.52
  text "c180hn180" at 399.403,66.802 h1.52
  text "2" at 251.718,62.992 h1.52
  text "62.00mil (1.575mm)" at 266.7,62.992 h1.52
  text "PTH" at 295.902,62.992 h1.52
  text "Round" at 308.751,62.992 h1.52
  text "Top Layer - Bottom Layer" at 327.389,62.992 h1.52
  text "Pad" at 365.478,62.992 h1.52
  text "Rounded" at 380.46,62.992 h1.52
  text "c236h157" at 399.403,62.992 h1.52
  text "2" at 251.718,59.182 h1.52
  text "122.05mil (3.100mm)" at 266.7,59.182 h1.52
  text "PTH" at 295.902,59.182 h1.52
  text "Round" at 308.751,59.182 h1.52
  text "Top Layer - Bottom Layer" at 327.389,59.182 h1.52
  text "Pad" at 365.478,59.182 h1.52
  text "Rounded" at 380.46,59.182 h1.52
  text "c465h310" at 399.403,59.182 h1.52
  text "A" at 238.13,58.928 h1.69
  text "2" at 251.718,55.372 h1.52
  text "128.00mil (3.251mm)" at 266.7,55.372 h1.52
  text "NPTH" at 295.902,55.372 h1.52
  text "Round" at 308.751,55.372 h1.52
  text "Top Layer - Bottom Layer" at 327.389,55.372 h1.52
  text "Pad" at 365.478,55.372 h1.52
  text "Rounded" at 380.46,55.372 h1.52
  text "c325hn325" at 399.403,55.372 h1.52
  text "4" at 251.718,51.562 h1.52
  text "32.68mil (0.830mm)" at 266.7,51.562 h1.52
  text "PTH" at 295.902,51.562 h1.52
  text "Round" at 308.751,51.562 h1.52
  text "Top Layer - Bottom Layer" at 327.389,51.562 h1.52
  text "Pad" at 365.478,51.562 h1.52
  text "(Mixed)" at 380.46,51.562 h1.52
  text "(Mixed)" at 399.403,51.562 h1.52
  text "4" at 251.718,47.752 h1.52
  text "45.00mil (1.143mm)" at 266.7,47.752 h1.52
  text "PTH" at 295.902,47.752 h1.52
  text "Round" at 308.751,47.752 h1.52
  text "Top Layer - Bottom Layer" at 327.389,47.752 h1.52
  text "Pad" at 365.478,47.752 h1.52
  text "Rounded" at 380.46,47.752 h1.52
  text "c171h114" at 399.403,47.752 h1.52
  text "4" at 251.718,43.942 h1.52
  text "125.98mil (3.200mm)" at 266.7,43.942 h1.52
  text "PTH" at 295.902,43.942 h1.52
  text "Round" at 308.751,43.942 h1.52
  text "Top Layer - Bottom Layer" at 327.389,43.942 h1.52
  text "Pad" at 365.478,43.942 h1.52
  text "Rounded" at 380.46,43.942 h1.52
  text "c700h320_672208418" at 399.403,43.942 h1.52
  text "6" at 251.718,40.132 h1.52
  text "45.28mil (1.150mm)" at 266.7,40.132 h1.52
  text "NPTH" at 295.902,40.132 h1.52
  text "Round" at 308.751,40.132 h1.52
  text "Top Layer - Bottom Layer" at 327.389,40.132 h1.52
  text "Pad" at 365.478,40.132 h1.52
  text "Rounded" at 380.46,40.132 h1.52
  text "c115hn115m115p0" at 399.403,40.132 h1.52
  text "9" at 251.718,36.322 h1.52
  text "35.43mil (0.900mm)" at 266.7,36.322 h1.52
  text "PTH" at 295.902,36.322 h1.52
  text "Round" at 308.751,36.322 h1.52
  text "Top Layer - Bottom Layer" at 327.389,36.322 h1.52
  text "Pad" at 365.478,36.322 h1.52
  text "(Mixed)" at 380.46,36.322 h1.52
  text "(Mixed)" at 399.403,36.322 h1.52
  text "12" at 251.718,32.512 h1.52
  text "40.00mil (1.016mm)" at 266.7,32.512 h1.52
  text "PTH" at 295.902,32.512 h1.52
  text "Round" at 308.751,32.512 h1.52
  text "Top Layer - Bottom Layer" at 327.389,32.512 h1.52
  text "Pad" at 365.478,32.512 h1.52
  text "Rounded" at 380.46,32.512 h1.52
  text "(Mixed)" at 399.403,32.512 h1.52
  text "244" at 251.718,28.702 h1.52
  text "39.37mil (1.000mm)" at 266.7,28.702 h1.52
  text "PTH" at 295.902,28.702 h1.52
  text "Round" at 308.751,28.702 h1.52
  text "Top Layer - Bottom Layer" at 327.389,28.702 h1.52
  text "Pad" at 365.478,28.702 h1.52
  text "(Mixed)" at 380.46,28.702 h1.52
  text "(Mixed)" at 399.403,28.702 h1.52
  text "629" at 251.718,24.892 h1.52
  text "7.87mil (0.200mm)" at 266.7,24.892 h1.52
  text "PTH" at 295.902,24.892 h1.52
  text "Round" at 308.751,24.892 h1.52
  text "Top Layer - Bottom Layer" at 327.389,24.892 h1.52
  text "Via" at 365.478,24.892 h1.52
  text "Rounded" at 380.46,24.892 h1.52
  text "lucas" at 399.403,24.892 h1.52
  text "8/20" at 428.859,24.892 h1.52
  text "921 Total" at 251.718,21.082 h1.52

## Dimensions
195,0 to 195,139 on Mechanical 1
0,139 to 195,139 on Mechanical 1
